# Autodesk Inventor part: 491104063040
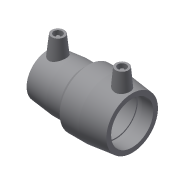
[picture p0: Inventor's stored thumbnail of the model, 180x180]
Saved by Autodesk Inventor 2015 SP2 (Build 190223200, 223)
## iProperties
Created: 2017-06
Part Number: 491104063040
Material: Generic
Description: PLASSON REDUCING COUPLER 63-40
Document SubType Name: Modeling
Designer: KIM
Mass: 54.8237 g
Surface Area: 155.252 cm^2
Volume: 54.8237 cm^3
Density: 1 g/cm^3
Appearance: Default
Author: KIM
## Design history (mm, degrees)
derived "491104.ipt"
feature "Solid1::491104.ipt"
tag "TaggingFeature1"
body "Solid1"
other parameters: "d0" = 119, "d2" = 56, "d3" = 44, "d4" = 26.4, "d5" = 50.4, "d8" = 168 deg, "d10" = 17.6, "d11" = 5.86667, "d13" = 119, "d14" = 17.6296, "d15" = 44, "d19" = 2.2, "d20" = 168 deg, "d22" = 108.92847, "d25" = 135 deg, "d29" = 49, "d30" = 15, "d31" = 45.22, "d34" = 6 deg, "d35" = 15, "d38" = 27, "d39" = 5 deg, "d41" = 4, "d42" = 14, "d43" = 0, "d45" = 4, "d46" = 14, "d47" = 0, "d48" = 56, "d49" = 63, "d50" = 82, "d52" = 36, "d53" = 22.8, "d54" = 7.6, "d55" = 168 deg, "d56" = 34.2, "d57" = 57, "d58" = 73.8, "d59" = 2.2, "d60" = 135 deg, "d61" = 59, "d62" = 15, "d64" = 4, "d66" = 5 deg, "d67" = 14, "d68" = 0, "d69" = 45.22, "d70" = 56, "d71" = 82, "d73" = 77.08, "d76" = 2.2, "d77" = 168 deg, "d78" = 63, "d79" = 2.2, "d80" = 57, "d81" = 36, "d82" = 52.64, "d83" = 120 deg, "d88" = 15, "d89" = 24.35, "d90" = 5 deg, "d92" = 4, "d93" = 14, "d94" = 0, "d95" = 3, "d96" = 0, "d97" = 3, "d98" = 0, "d99" = 12.76, "d100" = 3.19, "d101" = 51.0608, "d102" = 20 deg, "d103" = 16.53, "d104" = 4.1325, "d105" = 74.7676, "d106" = 3.60705, "d107" = 3, "d108" = 0, "d109" = 3, "d110" = 0, "L_" = 119, "L_2" = 44, "D_1" = 56, "A_1" = 49, "d_2" = 12, "L_1" = 57, "d_" = 63, "A_" = 59, "D_" = 82
